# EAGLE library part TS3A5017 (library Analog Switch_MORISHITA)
TS3A5017 analog switch Producted by TEXAS INSTRUMENTS
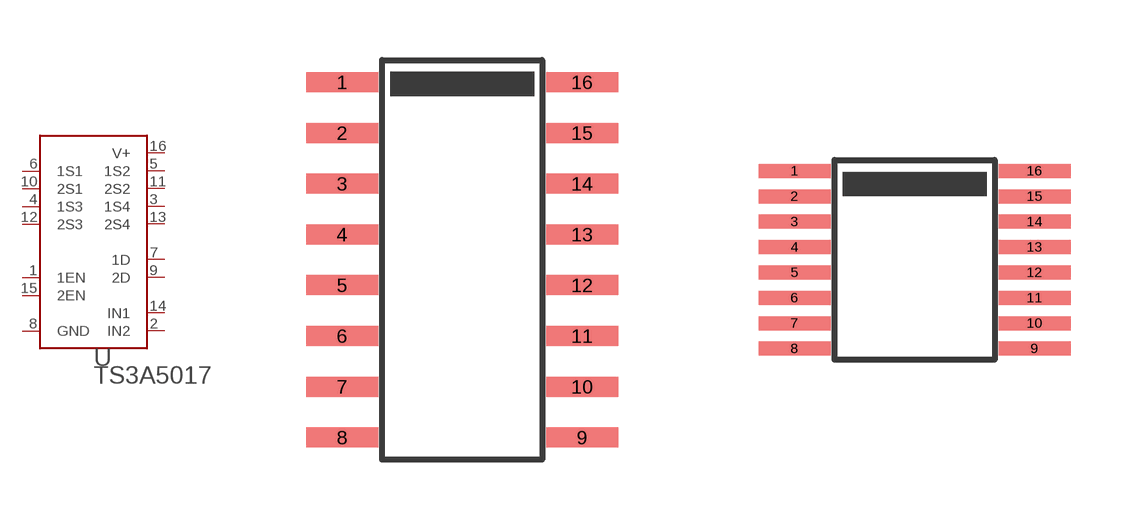
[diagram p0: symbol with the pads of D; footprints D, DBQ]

Designator prefix U

## TS3A5017-D  [D]
1  1EN  in
2  IN2  in
3  1S4
4  1S3
5  1S2
6  1S1
7  1D
8  GND  pwr
9  2D
10  2S1
11  2S2
12  2S3
13  2S4
14  IN1  in
15  2EN  in
16  V+  pwr

## TS3A5017-DBQ  [DBQ]
Pads as for D

## Footprint D (pad centres in mm)
TS3A5017 D package (R-PDSO-G16) TEXAS INSTRUMENTS 's plastic small-outline package
smd 1.8 x 0.5: 1 -3,4.445; 2 -3,3.175; 3 -3,1.905; 4 -3,0.635; 5 -3,-0.635; 6 -3,-1.905; 7 -3,-3.175; 8 -3,-4.445; 9 3,-4.445; 10 3,-3.175; 11 3,-1.905; 12 3,-0.635; 13 3,0.635; 14 3,1.905; 15 3,3.175; 16 3,4.445

## Footprint DBQ (pad centres in mm)
TS3A5017 DBQ package (R-PDSO-G16) TEXAS INSTRUMENTS 's plastic small-outline package
smd 1.8 x 0.35: 1 -3,2.223; 2 -3,1.587; 3 -3,0.953; 4 -3,0.318; 5 -3,-0.318; 6 -3,-0.953; 7 -3,-1.587; 8 -3,-2.223; 9 3,-2.223; 10 3,-1.587; 11 3,-0.953; 12 3,-0.318; 13 3,0.318; 14 3,0.953; 15 3,1.587; 16 3,2.223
